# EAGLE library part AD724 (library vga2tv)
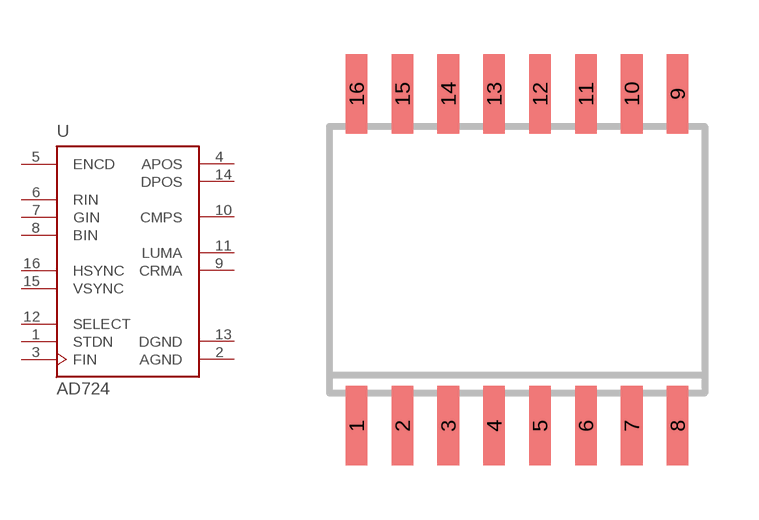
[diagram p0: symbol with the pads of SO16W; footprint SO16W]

Designator prefix -

## AD724JR  [SO16W]
1  STDN  in
2  AGND  pwr
3  FIN  in
4  APOS  pwr
5  ENCD  in
6  RIN  in
7  GIN  in
8  BIN  in
9  CRMA  out
10  CMPS  out
11  LUMA  out
12  SELECT  in
13  DGND  pwr
14  DPOS  pwr
15  VSYNC  in
16  HSYNC  in

## Footprint SO16W (pad centres in mm)
SO16 wide body 7.5 mm / JEDEC MS-013AA
smd 0.6 x 2.2: 1 -4.445,-4.6; 2 -3.175,-4.6; 3 -1.905,-4.6; 4 -0.635,-4.6; 5 0.635,-4.6; 6 1.905,-4.6; 7 3.175,-4.6; 8 4.445,-4.6; 9 4.445,4.6; 10 3.175,4.6; 11 1.905,4.6; 12 0.635,4.6; 13 -0.635,4.6; 14 -1.905,4.6; 15 -3.175,4.6; 16 -4.445,4.6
